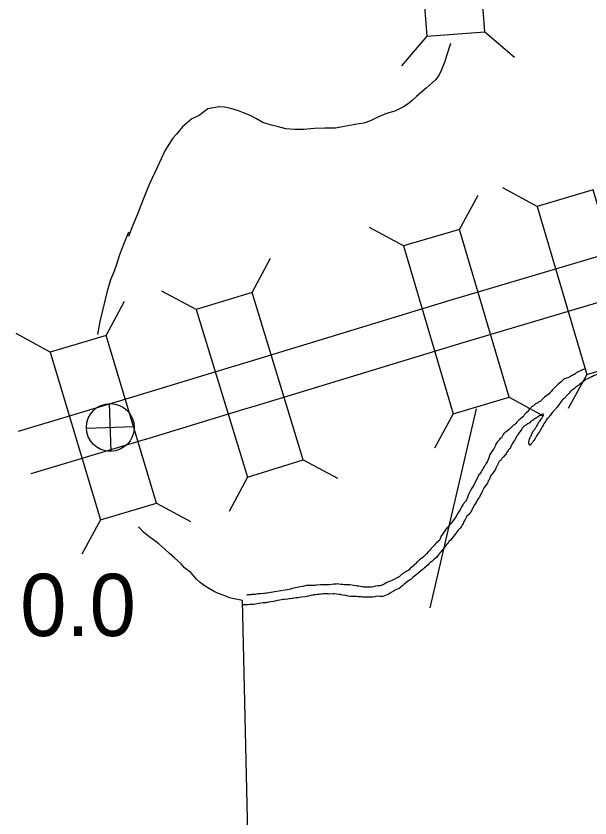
# Model space of a CAD drawing. Extents: x -939622 to -934222, y 1383701 to 1385301.
# Drawn here: x -936053.6 to -936041.91, y 1384199.54 to 1384215.87 of the extents above; entities that cross this region are included whole.
import ezdxf

# ---------------------------------------------------------------- set-up
doc = ezdxf.new("R2010")
doc.units = 0
for name, color, linetype in [('Level 15', 7, 'Continuous'), ('Level 2', 7, 'Continuous'), ('Level 20', 7, 'Continuous'), ('Level 25', 7, 'Continuous'), ('Level 26', 7, 'Continuous'), ('Level 9', 7, 'Continuous')]:
    doc.layers.add(name, color=color, linetype=linetype)

msp = doc.modelspace()

# ---------------------------------------------------------------- linework, layer by layer
at = {"layer": 'Level 15'}
for points in [[(-935995.123, 1384214.428), (-936000.214, 1384214.357), (-936000.32, 1384214.353), (-936004.423, 1384214.228), (-936007.337, 1384213.985), (-936008.235, 1384213.91), (-936010.631, 1384213.705), (-936016.167, 1384213.305), (-936024.073, 1384212.718), (-936024.475, 1384212.659), (-936031.409, 1384212.142), (-936032.182, 1384212.122), (-936037.332, 1384211.712), (-936039.788, 1384211.53), (-936039.973, 1384211.504), (-936042.042, 1384210.882), (-936044.763, 1384210.077), (-936048.966, 1384208.792), (-936049.22, 1384208.72), (-936051.228, 1384208.105)], [(-935995.11, 1384213.528), (-936000.193, 1384213.457), (-936000.292, 1384213.454), (-936004.372, 1384213.33), (-936007.262, 1384213.088), (-936008.16, 1384213.013), (-936010.56, 1384212.808), (-936016.101, 1384212.407), (-936023.974, 1384211.823), (-936024.376, 1384211.764), (-936031.364, 1384211.243), (-936032.135, 1384211.223), (-936037.263, 1384210.815), (-936039.693, 1384210.635), (-936039.78, 1384210.622), (-936041.784, 1384210.019), (-936044.504, 1384209.215), (-936048.71, 1384207.929), (-936048.965, 1384207.857), (-936050.964, 1384207.245)], [(-936051.225, 1384208.106), (-936053.551, 1384207.411)], [(-936050.967, 1384207.244), (-936053.297, 1384206.547)]]:
    msp.add_lwpolyline(points, dxfattribs=at)
at = {"layer": 'Level 2'}
for points in [[(-936044.755, 1384215.309), (-936044.762, 1384215.287), (-936044.825, 1384215.076), (-936044.868, 1384214.94), (-936044.94, 1384214.755)], [(-936044.94, 1384214.755), (-936044.989, 1384214.655), (-936045.06, 1384214.567), (-936045.128, 1384214.506), (-936045.249, 1384214.399), (-936045.335, 1384214.326), (-936045.445, 1384214.225), (-936045.533, 1384214.145), (-936045.613, 1384214.081), (-936045.711, 1384214.019), (-936045.887, 1384213.932), (-936046.057, 1384213.881), (-936046.233, 1384213.81), (-936046.382, 1384213.735), (-936046.516, 1384213.688), (-936046.69, 1384213.658), (-936046.914, 1384213.618), (-936047.094, 1384213.586), (-936047.307, 1384213.582), (-936047.52, 1384213.579), (-936047.736, 1384213.554), (-936047.919, 1384213.558), (-936048.102, 1384213.573), (-936048.253, 1384213.612), (-936048.424, 1384213.652), (-936048.569, 1384213.701), (-936048.699, 1384213.771), (-936048.845, 1384213.85), (-936048.968, 1384213.896), (-936049.068, 1384213.936), (-936049.222, 1384213.985), (-936049.351, 1384214.013), (-936049.462, 1384214.017), (-936049.69, 1384213.98), (-936049.871, 1384213.845), (-936050.017, 1384213.774), (-936050.209, 1384213.612), (-936050.327, 1384213.463), (-936050.404, 1384213.377), (-936050.568, 1384213.122), (-936050.719, 1384212.795), (-936050.884, 1384212.435), (-936051.023, 1384212.096), (-936051.124, 1384211.833), (-936051.216, 1384211.606), (-936051.309, 1384211.377)], [(-936051.309, 1384211.467), (-936051.392, 1384211.249), (-936051.49, 1384211.004), (-936051.55, 1384210.811), (-936051.599, 1384210.672), (-936051.674, 1384210.494), (-936051.743, 1384210.267), (-936051.839, 1384209.875), (-936051.892, 1384209.646), (-936051.937, 1384209.384)], [(-936048.986, 1384203.967), (-936049.154, 1384204), (-936049.19, 1384204.009), (-936049.25, 1384204.023), (-936049.326, 1384204.055), (-936049.383, 1384204.078), (-936049.498, 1384204.121), (-936049.574, 1384204.159), (-936049.655, 1384204.206), (-936049.746, 1384204.264), (-936049.847, 1384204.338), (-936049.913, 1384204.394), (-936050.039, 1384204.539), (-936050.166, 1384204.636), (-936050.237, 1384204.719), (-936050.368, 1384204.838), (-936050.474, 1384204.926), (-936050.565, 1384205.012), (-936050.687, 1384205.121), (-936050.796, 1384205.203), (-936050.863, 1384205.25), (-936050.951, 1384205.318), (-936051.006, 1384205.365), (-936051.082, 1384205.451), (-936051.098, 1384205.469)], [(-936048.438, 1384163.137), (-936048.444, 1384164.594), (-936048.45, 1384165.18), (-936048.542, 1384172.387), (-936048.531, 1384172.989), (-936048.635, 1384180.44), (-936048.66, 1384181.073), (-936048.769, 1384188.392), (-936048.777, 1384188.942), (-936048.812, 1384196.316), (-936048.823, 1384196.862), (-936048.986, 1384203.967)]]:
    msp.add_lwpolyline(points, dxfattribs=at)
at = {"layer": 'Level 20'}
for p, q in [((-936044.05, 1384215.547), (-936043.448, 1384215.032)), ((-936045.234, 1384215.455), (-936045.749, 1384214.854)), ((-936042.988, 1384211.991), (-936043.684, 1384212.369)), ((-936044.569, 1384211.524), (-936044.191, 1384212.219)), ((-936045.709, 1384211.187), (-936046.404, 1384211.565)), ((-936048.791, 1384210.239), (-936048.419, 1384210.938)), ((-936049.927, 1384209.891), (-936050.626, 1384210.263)), ((-936051.761, 1384209.365), (-936051.385, 1384210.062)), ((-936052.899, 1384209.025), (-936053.596, 1384209.401)), ((-936041.978, 1384208.573), (-936042.356, 1384207.877)), ((-936043.559, 1384208.106), (-936042.863, 1384207.728)), ((-936045.164, 1384203.818), (-936044.225, 1384207.871)), ((-936044.698, 1384207.769), (-936045.077, 1384207.073)), ((-936047.749, 1384206.83), (-936047.049, 1384206.459)), ((-936048.885, 1384206.483), (-936049.257, 1384205.784)), ((-936050.74, 1384205.951), (-936050.043, 1384205.575)), ((-936051.878, 1384205.61), (-936052.254, 1384204.913))]:
    msp.add_line(p, q, dxfattribs=at)
for points in [[(-936045.51, 1384219.009), (-936045.234, 1384215.455), (-936044.05, 1384215.547), (-936044.325, 1384219.1)], [(-936042.988, 1384211.991), (-936041.978, 1384208.573), (-936040.838, 1384208.91), (-936041.849, 1384212.328)], [(-936043.559, 1384208.106), (-936044.569, 1384211.524), (-936045.709, 1384211.187), (-936044.698, 1384207.769)], [(-936047.749, 1384206.83), (-936048.791, 1384210.239), (-936049.927, 1384209.891), (-936048.885, 1384206.483)], [(-936052.899, 1384209.025), (-936051.878, 1384205.61), (-936050.74, 1384205.951), (-936051.761, 1384209.365)]]:
    msp.add_lwpolyline(points, close=True, dxfattribs=at)
at = {"layer": 'Level 26'}
for p, q in [((-936051.66, 1384207.005), (-936051.696, 1384207.979)), ((-936052.166, 1384207.474), (-936051.191, 1384207.51))]:
    msp.add_line(p, q, dxfattribs=at)
msp.add_circle((-936051.678, 1384207.492), 0.487, dxfattribs=at)
at = {"layer": 'Level 9'}
for points in [[(-936041.997, 1384208.684), (-936042.016, 1384208.68), (-936042.049, 1384208.67), (-936042.081, 1384208.657), (-936042.102, 1384208.647), (-936042.123, 1384208.64), (-936042.17, 1384208.617), (-936042.179, 1384208.611), (-936042.193, 1384208.602), (-936042.214, 1384208.586), (-936042.225, 1384208.573), (-936042.24, 1384208.567), (-936042.272, 1384208.548), (-936042.287, 1384208.544), (-936042.308, 1384208.531), (-936042.328, 1384208.522), (-936042.346, 1384208.512), (-936042.393, 1384208.498), (-936042.417, 1384208.489), (-936042.432, 1384208.482), (-936042.452, 1384208.466), (-936042.478, 1384208.444), (-936042.501, 1384208.423), (-936042.542, 1384208.388)], [(-936042.087, 1384208.401), (-936042.006, 1384208.47)], [(-936041.704, 1384208.586), (-936041.711, 1384208.585), (-936041.737, 1384208.578), (-936041.755, 1384208.572), (-936041.782, 1384208.565), (-936041.826, 1384208.548), (-936041.861, 1384208.532), (-936041.882, 1384208.522), (-936041.891, 1384208.519), (-936041.903, 1384208.51), (-936041.911, 1384208.506), (-936041.923, 1384208.5), (-936041.979, 1384208.477), (-936042.006, 1384208.47)], [(-936042.087, 1384208.401), (-936042.102, 1384208.385), (-936042.125, 1384208.364), (-936042.145, 1384208.348), (-936042.169, 1384208.335), (-936042.181, 1384208.326), (-936042.201, 1384208.31), (-936042.227, 1384208.285), (-936042.251, 1384208.269), (-936042.28, 1384208.247), (-936042.315, 1384208.216), (-936042.338, 1384208.191), (-936042.349, 1384208.178), (-936042.366, 1384208.16), (-936042.395, 1384208.132), (-936042.407, 1384208.116), (-936042.424, 1384208.098), (-936042.439, 1384208.082), (-936042.473, 1384208.051), (-936042.488, 1384208.038), (-936042.514, 1384208.001), (-936042.531, 1384207.974), (-936042.542, 1384207.955), (-936042.551, 1384207.943), (-936042.579, 1384207.906), (-936042.605, 1384207.881), (-936042.614, 1384207.866), (-936042.64, 1384207.838), (-936042.654, 1384207.822), (-936042.677, 1384207.8), (-936042.709, 1384207.757), (-936042.726, 1384207.738), (-936042.743, 1384207.714), (-936042.757, 1384207.689), (-936042.789, 1384207.658), (-936042.803, 1384207.637), (-936042.821, 1384207.615), (-936042.855, 1384207.566), (-936042.866, 1384207.541), (-936042.886, 1384207.502), (-936042.897, 1384207.477), (-936042.928, 1384207.428), (-936042.936, 1384207.41), (-936042.953, 1384207.388), (-936042.971, 1384207.363), (-936042.976, 1384207.354), (-936042.985, 1384207.339), (-936043.002, 1384207.311), (-936043.013, 1384207.293), (-936043.036, 1384207.253), (-936043.053, 1384207.228), (-936043.067, 1384207.213), (-936043.076, 1384207.197), (-936043.081, 1384207.188), (-936043.09, 1384207.176), (-936043.099, 1384207.17), (-936043.107, 1384207.157), (-936043.13, 1384207.132), (-936043.133, 1384207.129), (-936043.139, 1384207.129), (-936043.145, 1384207.135), (-936043.148, 1384207.141), (-936043.152, 1384207.159), (-936043.156, 1384207.18), (-936043.157, 1384207.204), (-936043.151, 1384207.222)], [(-936042.56, 1384208.372), (-936042.684, 1384208.251)], [(-936042.542, 1384208.388), (-936042.56, 1384208.372)], [(-936042.684, 1384208.251), (-936042.698, 1384208.232), (-936042.724, 1384208.201), (-936042.744, 1384208.177), (-936042.838, 1384208.11), (-936042.858, 1384208.089), (-936042.861, 1384208.085), (-936042.873, 1384208.076), (-936042.887, 1384208.063), (-936042.893, 1384208.057), (-936042.919, 1384208.029), (-936042.945, 1384208.013), (-936042.954, 1384208.01), (-936042.983, 1384207.988), (-936043.019, 1384207.972), (-936043.065, 1384207.934), (-936043.1, 1384207.909), (-936043.112, 1384207.896), (-936043.135, 1384207.874), (-936043.141, 1384207.868), (-936043.158, 1384207.85), (-936043.166, 1384207.825), (-936043.213, 1384207.788), (-936043.233, 1384207.766), (-936043.245, 1384207.753), (-936043.262, 1384207.729), (-936043.282, 1384207.707), (-936043.326, 1384207.669), (-936043.363, 1384207.638), (-936043.381, 1384207.619), (-936043.407, 1384207.595), (-936043.424, 1384207.573), (-936043.444, 1384207.554), (-936043.468, 1384207.538), (-936043.491, 1384207.519), (-936043.526, 1384207.485), (-936043.534, 1384207.476), (-936043.549, 1384207.46), (-936043.59, 1384207.426), (-936043.622, 1384207.404), (-936043.642, 1384207.394), (-936043.666, 1384207.372), (-936043.683, 1384207.347), (-936043.702, 1384207.308), (-936043.716, 1384207.283), (-936043.745, 1384207.258), (-936043.763, 1384207.243), (-936043.771, 1384207.227), (-936043.786, 1384207.206), (-936043.8, 1384207.19), (-936043.814, 1384207.169), (-936043.834, 1384207.135), (-936043.842, 1384207.114), (-936043.862, 1384207.071), (-936043.873, 1384207.058), (-936043.899, 1384207.021), (-936043.921, 1384206.982), (-936043.924, 1384206.975), (-936043.95, 1384206.938), (-936043.966, 1384206.899), (-936043.966, 1384206.896), (-936043.975, 1384206.871), (-936043.98, 1384206.856), (-936043.985, 1384206.841), (-936043.999, 1384206.808), (-936044.019, 1384206.774), (-936044.03, 1384206.752), (-936044.039, 1384206.737), (-936044.047, 1384206.725), (-936044.056, 1384206.712), (-936044.064, 1384206.697), (-936044.09, 1384206.663), (-936044.104, 1384206.636), (-936044.115, 1384206.617), (-936044.129, 1384206.587), (-936044.141, 1384206.571), (-936044.154, 1384206.546)], [(-936043.151, 1384207.222), (-936043.143, 1384207.252), (-936043.132, 1384207.277), (-936043.13, 1384207.286), (-936043.124, 1384207.298), (-936043.118, 1384207.31), (-936043.113, 1384207.319), (-936043.105, 1384207.341), (-936043.102, 1384207.356), (-936043.099, 1384207.362), (-936043.085, 1384207.383), (-936043.077, 1384207.402), (-936043.074, 1384207.405), (-936043.062, 1384207.42), (-936043.057, 1384207.429), (-936043.048, 1384207.442), (-936043.037, 1384207.457), (-936043.028, 1384207.467), (-936043.02, 1384207.482), (-936043.014, 1384207.491), (-936043.008, 1384207.497), (-936043.003, 1384207.512), (-936042.988, 1384207.534), (-936042.983, 1384207.546), (-936042.969, 1384207.565), (-936042.958, 1384207.595), (-936042.949, 1384207.604), (-936042.943, 1384207.617), (-936042.935, 1384207.623), (-936042.923, 1384207.638), (-936042.909, 1384207.66), (-936042.9, 1384207.672), (-936042.892, 1384207.691), (-936042.889, 1384207.691), (-936042.875, 1384207.715), (-936042.872, 1384207.724), (-936042.867, 1384207.731), (-936042.864, 1384207.737), (-936042.858, 1384207.743), (-936042.855, 1384207.755), (-936042.871, 1384207.76), (-936042.874, 1384207.763), (-936042.88, 1384207.763), (-936042.886, 1384207.76), (-936042.894, 1384207.754), (-936042.903, 1384207.747), (-936042.909, 1384207.741), (-936042.915, 1384207.738), (-936042.924, 1384207.735), (-936042.932, 1384207.728), (-936042.938, 1384207.725), (-936042.959, 1384207.712), (-936042.979, 1384207.7), (-936043, 1384207.687), (-936043.012, 1384207.68), (-936043.038, 1384207.668), (-936043.05, 1384207.658), (-936043.064, 1384207.649), (-936043.067, 1384207.645), (-936043.085, 1384207.63), (-936043.102, 1384207.617), (-936043.123, 1384207.604), (-936043.14, 1384207.589), (-936043.152, 1384207.582), (-936043.172, 1384207.57), (-936043.208, 1384207.547), (-936043.243, 1384207.525), (-936043.254, 1384207.516), (-936043.257, 1384207.513), (-936043.278, 1384207.494), (-936043.292, 1384207.478), (-936043.3, 1384207.454), (-936043.309, 1384207.448), (-936043.323, 1384207.429), (-936043.346, 1384207.398), (-936043.36, 1384207.377), (-936043.38, 1384207.346), (-936043.389, 1384207.328), (-936043.4, 1384207.315), (-936043.437, 1384207.254), (-936043.451, 1384207.226), (-936043.471, 1384207.199), (-936043.485, 1384207.177), (-936043.51, 1384207.131), (-936043.521, 1384207.101), (-936043.533, 1384207.082), (-936043.547, 1384207.061), (-936043.555, 1384207.048), (-936043.57, 1384207.033), (-936043.575, 1384207.021), (-936043.59, 1384207.005), (-936043.61, 1384206.974), (-936043.621, 1384206.956), (-936043.635, 1384206.937), (-936043.644, 1384206.928), (-936043.673, 1384206.897), (-936043.687, 1384206.882), (-936043.705, 1384206.857), (-936043.722, 1384206.835), (-936043.736, 1384206.82), (-936043.754, 1384206.804)], [(-936043.826, 1384206.654), (-936043.835, 1384206.645), (-936043.849, 1384206.62), (-936043.875, 1384206.58), (-936043.892, 1384206.562), (-936043.906, 1384206.54), (-936043.923, 1384206.519), (-936043.935, 1384206.497), (-936043.957, 1384206.448), (-936043.968, 1384206.427), (-936043.982, 1384206.402), (-936043.993, 1384206.375), (-936044.002, 1384206.36), (-936044.022, 1384206.329), (-936044.047, 1384206.298), (-936044.067, 1384206.267), (-936044.084, 1384206.231), (-936044.112, 1384206.172), (-936044.123, 1384206.154), (-936044.14, 1384206.126), (-936044.149, 1384206.108), (-936044.165, 1384206.074), (-936044.174, 1384206.062), (-936044.188, 1384206.038), (-936044.208, 1384206.01), (-936044.222, 1384205.979), (-936044.233, 1384205.958), (-936044.259, 1384205.921), (-936044.267, 1384205.909), (-936044.276, 1384205.89), (-936044.293, 1384205.866), (-936044.304, 1384205.841), (-936044.321, 1384205.808), (-936044.341, 1384205.774), (-936044.378, 1384205.718), (-936044.418, 1384205.687), (-936044.432, 1384205.659), (-936044.446, 1384205.632), (-936044.455, 1384205.62), (-936044.486, 1384205.561), (-936044.494, 1384205.54), (-936044.505, 1384205.519), (-936044.531, 1384205.476), (-936044.554, 1384205.445), (-936044.603, 1384205.395), (-936044.628, 1384205.355), (-936044.648, 1384205.327), (-936044.68, 1384205.293), (-936044.697, 1384205.266), (-936044.752, 1384205.2), (-936044.784, 1384205.169), (-936044.795, 1384205.154), (-936044.815, 1384205.129), (-936044.827, 1384205.114), (-936044.844, 1384205.089), (-936044.858, 1384205.068), (-936044.875, 1384205.049), (-936044.924, 1384204.993), (-936044.95, 1384204.962), (-936044.961, 1384204.944), (-936044.984, 1384204.916), (-936044.989, 1384204.909)], [(-936043.826, 1384206.654), (-936043.754, 1384206.804)], [(-936044.179, 1384206.515), (-936044.198, 1384206.485), (-936044.228, 1384206.409), (-936044.267, 1384206.335), (-936044.279, 1384206.314), (-936044.318, 1384206.255), (-936044.344, 1384206.206), (-936044.369, 1384206.152), (-936044.386, 1384206.124), (-936044.41, 1384206.045), (-936044.419, 1384206.036), (-936044.427, 1384206.017), (-936044.435, 1384205.999), (-936044.447, 1384205.983), (-936044.498, 1384205.922), (-936044.501, 1384205.909), (-936044.507, 1384205.9)], [(-936044.179, 1384206.515), (-936044.154, 1384206.546)], [(-936044.507, 1384205.9), (-936044.527, 1384205.873), (-936044.549, 1384205.836), (-936044.558, 1384205.817), (-936044.578, 1384205.787), (-936044.592, 1384205.768), (-936044.606, 1384205.747), (-936044.614, 1384205.722), (-936044.645, 1384205.673), (-936044.671, 1384205.633), (-936044.697, 1384205.596), (-936044.711, 1384205.575), (-936044.731, 1384205.547), (-936044.734, 1384205.541), (-936044.766, 1384205.516), (-936044.789, 1384205.488), (-936044.816, 1384205.452)], [(-936044.963, 1384205.218), (-936044.94, 1384205.272), (-936044.816, 1384205.452)], [(-936044.97, 1384205.202), (-936044.988, 1384205.186), (-936045.043, 1384205.139), (-936045.063, 1384205.117), (-936045.086, 1384205.09), (-936045.127, 1384205.046), (-936045.15, 1384205.021), (-936045.17, 1384204.997), (-936045.199, 1384204.966), (-936045.239, 1384204.919), (-936045.257, 1384204.903), (-936045.3, 1384204.857), (-936045.338, 1384204.828), (-936045.361, 1384204.813), (-936045.384, 1384204.794), (-936045.416, 1384204.766), (-936045.44, 1384204.747), (-936045.463, 1384204.719), (-936045.477, 1384204.709), (-936045.48, 1384204.703), (-936045.489, 1384204.697), (-936045.515, 1384204.669), (-936045.529, 1384204.659), (-936045.564, 1384204.628), (-936045.582, 1384204.613), (-936045.596, 1384204.597), (-936045.611, 1384204.587), (-936045.617, 1384204.581), (-936045.64, 1384204.568), (-936045.661, 1384204.556), (-936045.672, 1384204.552), (-936045.696, 1384204.533), (-936045.716, 1384204.518), (-936045.728, 1384204.511), (-936045.734, 1384204.505), (-936045.748, 1384204.499), (-936045.778, 1384204.473), (-936045.792, 1384204.46)], [(-936044.97, 1384205.202), (-936044.963, 1384205.218)], [(-936045.023, 1384204.868), (-936045.039, 1384204.848), (-936045.065, 1384204.826), (-936045.097, 1384204.798), (-936045.132, 1384204.766), (-936045.164, 1384204.741), (-936045.184, 1384204.72), (-936045.207, 1384204.698), (-936045.251, 1384204.657), (-936045.28, 1384204.632), (-936045.309, 1384204.61), (-936045.327, 1384204.594), (-936045.338, 1384204.585), (-936045.417, 1384204.516), (-936045.425, 1384204.51), (-936045.449, 1384204.491), (-936045.478, 1384204.469), (-936045.519, 1384204.437), (-936045.562, 1384204.4), (-936045.586, 1384204.384), (-936045.609, 1384204.371), (-936045.635, 1384204.349), (-936045.659, 1384204.33), (-936045.676, 1384204.318), (-936045.694, 1384204.302), (-936045.729, 1384204.271), (-936045.749, 1384204.255), (-936045.767, 1384204.245), (-936045.769, 1384204.236), (-936045.799, 1384204.217), (-936045.852, 1384204.194), (-936045.89, 1384204.175), (-936045.91, 1384204.162), (-936045.96, 1384204.131), (-936045.978, 1384204.121), (-936045.998, 1384204.108)], [(-936044.989, 1384204.909), (-936045.023, 1384204.868)], [(-936045.831, 1384204.436), (-936045.86, 1384204.423), (-936045.871, 1384204.413), (-936045.907, 1384204.4), (-936045.948, 1384204.374), (-936045.951, 1384204.371), (-936045.989, 1384204.361), (-936046.013, 1384204.351), (-936046.051, 1384204.338), (-936046.051, 1384204.335), (-936046.104, 1384204.3), (-936046.13, 1384204.287), (-936046.187, 1384204.27), (-936046.225, 1384204.266), (-936046.276, 1384204.258), (-936046.327, 1384204.25), (-936046.356, 1384204.243), (-936046.383, 1384204.242), (-936046.437, 1384204.24), (-936046.47, 1384204.239), (-936046.509, 1384204.244), (-936046.53, 1384204.246), (-936046.551, 1384204.251), (-936046.59, 1384204.256), (-936046.615, 1384204.261), (-936046.648, 1384204.263), (-936046.666, 1384204.265), (-936046.723, 1384204.275), (-936046.762, 1384204.28), (-936046.801, 1384204.285), (-936046.849, 1384204.286), (-936046.867, 1384204.288), (-936046.876, 1384204.288), (-936046.891, 1384204.287), (-936046.912, 1384204.29), (-936046.918, 1384204.289)], [(-936045.831, 1384204.436), (-936045.792, 1384204.46)], [(-936046.918, 1384204.289), (-936046.942, 1384204.292), (-936046.969, 1384204.294), (-936046.987, 1384204.296), (-936047.026, 1384204.304), (-936047.059, 1384204.306), (-936047.08, 1384204.305), (-936047.113, 1384204.301), (-936047.125, 1384204.3), (-936047.167, 1384204.296), (-936047.167, 1384204.293), (-936047.17, 1384204.293), (-936047.214, 1384204.291), (-936047.238, 1384204.29), (-936047.292, 1384204.291), (-936047.307, 1384204.291), (-936047.334, 1384204.287), (-936047.355, 1384204.286), (-936047.382, 1384204.285), (-936047.4, 1384204.285), (-936047.471, 1384204.279), (-936047.501, 1384204.278), (-936047.534, 1384204.277), (-936047.567, 1384204.276), (-936047.591, 1384204.275), (-936047.63, 1384204.274), (-936047.657, 1384204.273), (-936047.684, 1384204.272), (-936047.705, 1384204.268), (-936047.737, 1384204.261), (-936047.755, 1384204.257), (-936047.803, 1384204.25), (-936047.841, 1384204.242), (-936047.874, 1384204.235), (-936047.91, 1384204.225), (-936047.945, 1384204.218), (-936047.993, 1384204.207), (-936048.011, 1384204.2), (-936048.038, 1384204.196), (-936048.073, 1384204.186), (-936048.118, 1384204.178), (-936048.204, 1384204.166), (-936048.249, 1384204.159), (-936048.335, 1384204.147), (-936048.404, 1384204.135), (-936048.416, 1384204.132), (-936048.451, 1384204.125), (-936048.481, 1384204.121), (-936048.505, 1384204.117), (-936048.538, 1384204.113), (-936048.549, 1384204.109), (-936048.621, 1384204.104), (-936048.666, 1384204.102), (-936048.708, 1384204.098), (-936048.726, 1384204.094), (-936048.761, 1384204.09), (-936048.797, 1384204.089), (-936048.815, 1384204.085), (-936048.83, 1384204.084), (-936048.863, 1384204.083), (-936048.875, 1384204.083), (-936048.878, 1384204.083), (-936048.884, 1384204.083), (-936048.893, 1384204.079), (-936048.893, 1384204.082)], [(-936045.998, 1384204.108), (-936046.031, 1384204.092), (-936046.06, 1384204.076), (-936046.09, 1384204.063), (-936046.134, 1384204.052), (-936046.137, 1384204.052), (-936046.176, 1384204.054), (-936046.188, 1384204.053), (-936046.242, 1384204.055), (-936046.272, 1384204.048), (-936046.295, 1384204.041), (-936046.331, 1384204.036), (-936046.37, 1384204.035), (-936046.388, 1384204.034), (-936046.406, 1384204.037), (-936046.46, 1384204.038), (-936046.49, 1384204.037), (-936046.541, 1384204.038), (-936046.571, 1384204.043), (-936046.601, 1384204.045), (-936046.631, 1384204.047), (-936046.658, 1384204.049), (-936046.712, 1384204.053), (-936046.73, 1384204.053), (-936046.79, 1384204.053), (-936046.835, 1384204.058), (-936046.88, 1384204.068), (-936046.898, 1384204.071), (-936046.944, 1384204.078), (-936046.98, 1384204.083), (-936046.989, 1384204.089), (-936047.019, 1384204.094), (-936047.07, 1384204.098), (-936047.121, 1384204.102), (-936047.139, 1384204.104), (-936047.226, 1384204.101), (-936047.25, 1384204.104), (-936047.28, 1384204.103), (-936047.343, 1384204.103), (-936047.378, 1384204.099), (-936047.396, 1384204.098), (-936047.426, 1384204.091), (-936047.468, 1384204.09), (-936047.495, 1384204.086), (-936047.536, 1384204.082), (-936047.557, 1384204.078), (-936047.587, 1384204.074), (-936047.602, 1384204.07), (-936047.623, 1384204.064), (-936047.646, 1384204.057), (-936047.682, 1384204.052), (-936047.712, 1384204.045), (-936047.784, 1384204.04), (-936047.819, 1384204.033), (-936047.855, 1384204.025), (-936047.9, 1384204.021), (-936047.93, 1384204.02), (-936047.959, 1384204.013), (-936047.983, 1384204.009), (-936048.019, 1384204.005), (-936048.034, 1384204.001), (-936048.064, 1384203.997), (-936048.129, 1384203.992), (-936048.144, 1384203.991), (-936048.162, 1384203.988), (-936048.195, 1384203.983), (-936048.225, 1384203.979), (-936048.281, 1384203.968), (-936048.329, 1384203.955), (-936048.349, 1384203.948), (-936048.409, 1384203.943), (-936048.457, 1384203.935), (-936048.477, 1384203.929), (-936048.507, 1384203.924), (-936048.564, 1384203.919), (-936048.614, 1384203.912), (-936048.65, 1384203.91), (-936048.763, 1384203.891), (-936048.802, 1384203.887), (-936048.82, 1384203.886), (-936048.835, 1384203.886), (-936048.874, 1384203.882), (-936048.922, 1384203.88), (-936048.931, 1384203.88), (-936048.961, 1384203.879), (-936048.979, 1384203.878), (-936048.982, 1384203.881)]]:
    msp.add_lwpolyline(points, dxfattribs=at)

# ---------------------------------------------------------------- texts
at = {"layer": 'Level 25'}
msp.add_text('0.0', height=1.2672, dxfattribs=at).set_placement((-936053.512, 1384203.246))

doc.saveas('drawing.dxf')
